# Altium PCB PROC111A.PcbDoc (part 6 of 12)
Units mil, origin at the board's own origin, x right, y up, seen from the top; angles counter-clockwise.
Board outline 7700 x 2300 mil, 6 copper layers (Top Layer, GND 1, SIG 1, SIG 2, GND 2, Bottom Layer), stack 61.062 mil thick; 841 components, 632 nets, 2914 pads, 1627 vias.
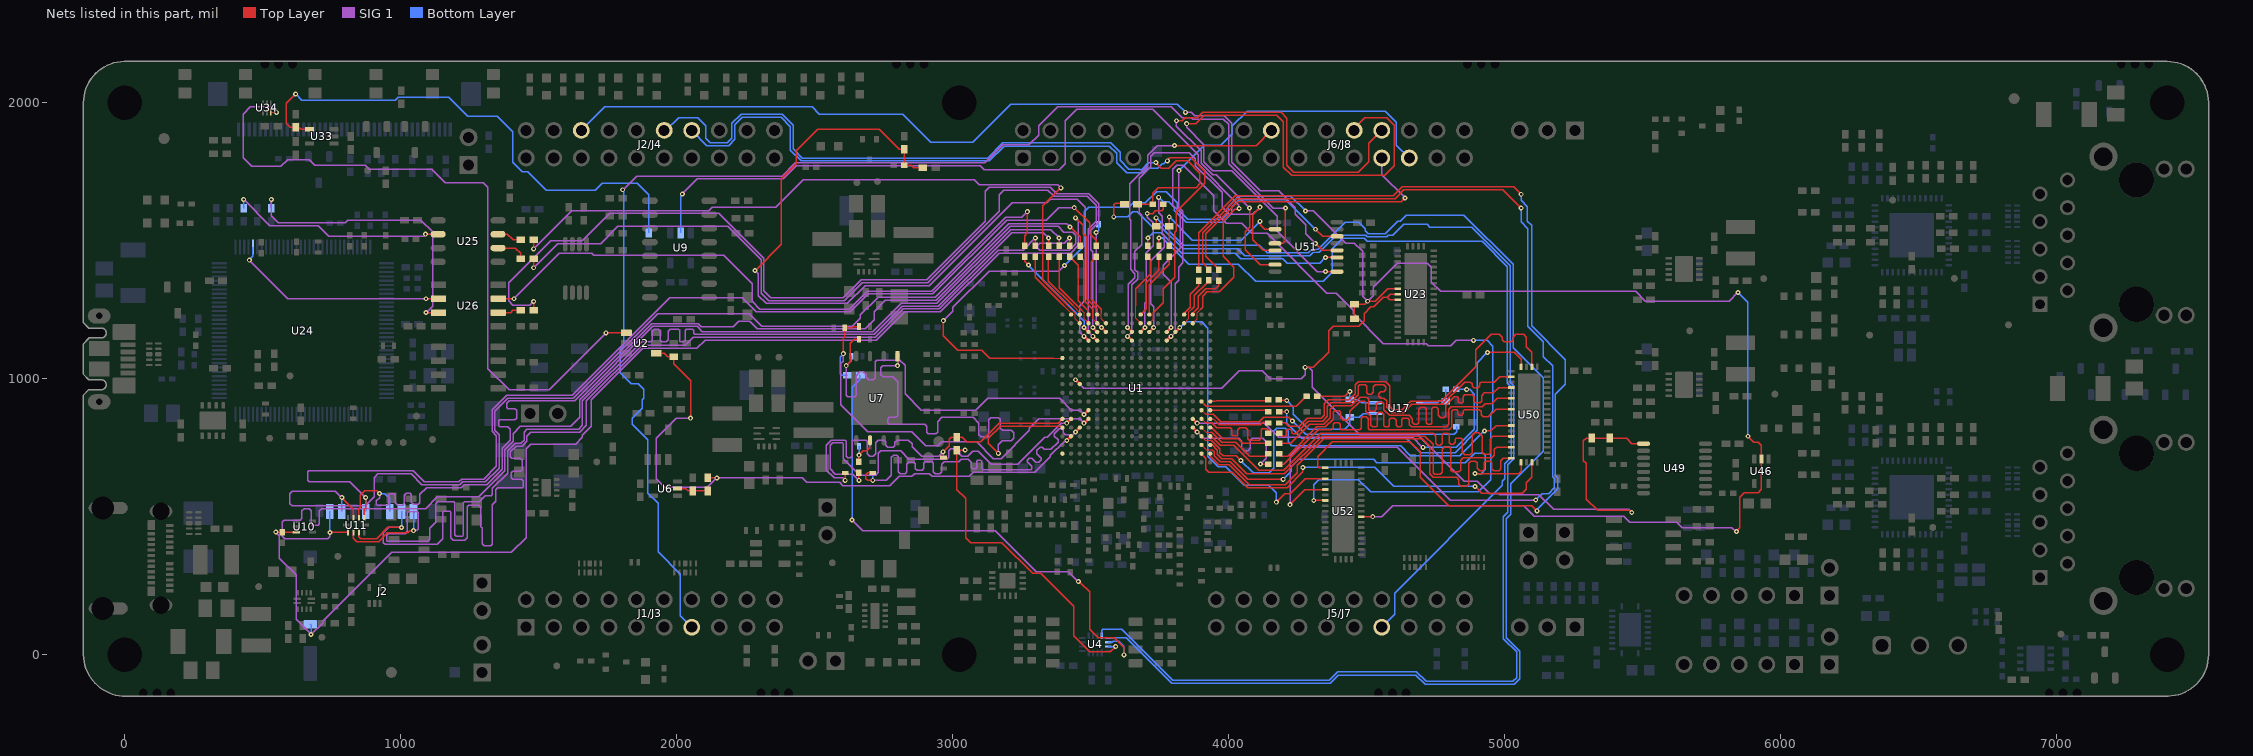
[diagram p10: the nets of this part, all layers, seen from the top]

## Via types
v1: diameter 18, hole 8, Top Layer to Bottom Layer, tented both sides, 1523 vias
v2: diameter 19.68, hole 7.87, Top Layer to Bottom Layer, tented both sides, 104 vias

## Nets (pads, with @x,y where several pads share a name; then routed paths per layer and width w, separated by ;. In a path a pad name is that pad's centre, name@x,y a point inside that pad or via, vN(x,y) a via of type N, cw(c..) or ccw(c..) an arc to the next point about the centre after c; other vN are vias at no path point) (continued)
AM263_MDIO0_MDC_R: R61.2 U1.M17 | length 995.7
  Top Layer w4: U1.M17@3901.07,886.34 3915.59,871.81
  Top Layer w5.3: 3915.59,871.81 3943.38,871.81 3971.5,843.69 4109.91,843.69 4126.4,860.18 4216.95,860.18 v1(4230,847.13)
  Bottom Layer w5.3: v1(4230,847.13) 4278.34,798.79 4816.19,798.79 4825,807.6 4825,825.75 R61.2@4824.96,825.79
AM263_MDIO0_MDIO: R62.1 R64.1 U17.7 | length 125.7
  Bottom Layer w5.3: U17.7@4705.28,913.43 4754.79,913.43 4759.79,918.43 R64.1@4785.59,918.43 R62.1@4785.59,961.7
AM263_MDIO0_MDIO_R: R62.2 U1.N16 | length 1289.2
  Top Layer w10: U1.N16@3869.57,854.84 v1(3885.32,839.09)
  SIG 1 w4.75: v1(3885.32,839.09) 4128.7,839.09 4180.25,787.54 4665.65,787.54 4701.26,751.93 v1(4703.62,751.93)
  Bottom Layer w5.3: v1(4703.62,751.93) 4824.46,751.93 4890,817.46 4890,944.07 4872.46,961.61 v1(4861.92,961.61) 4861.82,961.7 R62.2@4824.96,961.7
AM263_MMC0_CD: J2.9 R40.1 U1.A5 U10.3 | length 4633.3
  Top Layer w5.3: v1(547.23,444.53) R40.1@570.7,444.53 U10.3@613.65,444.53 ; v1(3444.38,1583.21) 3472,1555.59 3472,1525.5 3485,1512.5 3485,1289.81 3523.12,1251.69 U1.A5@3523.12,1232.8
  SIG 1 w4.75: v1(675.15,73.7) 716.63,115.18 716.63,121.7 747.2,152.28 cw(c763.55,142.11) 753.37,158.45 966.68,371.75 1200.92,371.75 1201.9,370.76 1400.23,370.76 1454.17,424.7 1454.17,747.3 1470.09,763.23 1633.46,763.23 1658.14,787.9 1658.14,795.88 1690,827.74 1690,923.63 1876.56,1110.2 2072.97,1110.2 2103.28,1140.51 2723.12,1140.51 2825.46,1242.85 2955.2,1242.85 3168.05,1455.7 3426.54,1455.7 3455.2,1484.37 3455.2,1572.39 v1(3444.38,1583.21)
  SIG 1 w5.3: v1(547.23,444.53) 559.83,431.92 559.83,350.32 620.88,289.27 620.88,127.96 v1(675.15,73.7)
  Bottom Layer w5.3: J2.9@671.97,110.16 675.15,106.98 v1(675.15,73.7)
AM263_MMC0_CLK: J2.5 R33.2 U11.1 | length 3953.5
  Top Layer w5.3: U11.1@867.72,496.58 867.72,526.24 872.76,531.27 v1(872.76,569.45) ; v1(3440,1620) 3495.4,1564.6 3495.4,1526.1 3519,1502.5 R33.2@3519,1482.17
  SIG 1 w4.75: v1(872.76,569.45) 814.65,627.56 668.52,627.56 663.07,633.01 663.07,664 665.85,666.78 1044.33,666.78 1084.97,626.15 1210.08,626.15 1220.34,636.41 1300.64,636.41 1346.64,682.41 1346.64,793.48 1330.7,809.42 1330.7,887.14 1383.73,940.16 1621.25,940.16 1974.63,1293.54 2237.5,1293.54 2288.35,1242.69 2629.26,1242.69 2694.29,1307.71 2927.71,1307.71 3194.99,1574.99 3338.2,1574.99 3383.21,1620 v1(3440,1620)
  Bottom Layer w5.3: J2.5@872.76,519.61 v1(872.76,569.45)
AM263_MMC0_CLK_R: R33.1 U1.B6 | length 271.2
  Top Layer w4: 3537.64,1237.89 3537.64,1218.27 U1.B6@3554.61,1201.3
  Top Layer w5.3: R33.1@3519,1442.8 3500.97,1424.76 3500.97,1288.83 3537.64,1252.16 3537.64,1237.89
AM263_MMC0_CMD: J2.3 R34.2 U11.2 | length 4077.1
  Top Layer w5.3: U11.2@848.04,496.58 848.04,528.5 853.23,533.69 853.23,577.54 869.46,593.77 913.58,593.77 v1(923.09,584.25) ; R34.2@3423,1482.17 v1(3423,1510.23)
  SIG 1 w4.75: v1(923.09,584.25) 923.04,584.2 923.04,568.75 911.91,557.62 911.91,544.51 914.7,541.73 951.21,541.73 955.9,546.42 955.9,578.94 961.21,584.25 975.79,584.25 980,580.04 980,550.86 989.13,541.73 1006.38,541.73 1013.31,548.66 1013.31,578.44 1019.87,585 1033.4,585 1038.36,580.04 1038.36,552.76 1046.12,545 1063.96,545 1069.48,550.51 1069.48,581.06 1093.74,605.32 1219.01,605.32 1230,616.31 1311.05,616.31 1366.74,672 1366.74,747.64 1396.64,777.54 1396.64,817.87 1388.34,826.17 1357.78,826.17 1355,828.95 1355,848.02 1357.78,850.8 1412.66,850.8 1419.52,857.67 1419.52,885.31 1413.06,891.78 1388.15,891.78 1383.19,896.74 1383.19,911.2 1392.05,920.06 1629.58,920.06 1909.52,1200 2077.48,1200 2088.4,1189.08 2203.92,1189.08 2223.99,1209.16 2263.92,1209.16 2292.37,1180.71 2682.56,1180.71 2714.93,1213.08 2714.93,1243.43 2756.08,1284.58 2940.08,1284.58 3207.45,1551.95 3381.28,1551.95 3402.48,1530.75 3434.54,1530.75 3445.15,1520.14 3445.15,1488.53 3422.37,1465.75 3315,1465.75 3308.15,1472.6 3308.15,1484.13 3315,1490.98 3403.75,1490.98 v1(3423,1510.23)
  Bottom Layer w5.3: v1(923.09,584.25) 942.45,584.25 959.37,567.33 J2.3@959.37,519.61
AM263_MMC0_CMD_R: R34.1 U1.A4 | length 238.4
  Top Layer w5.3: R34.1@3423,1442.8 3455,1410.8 3455,1283.11 3489.62,1248.48 3489.62,1234.79 U1.A4@3491.62,1232.8
AM263_MMC0_D0: J2.7 R35.2 U11.3 | length 3978.7
  Top Layer w5.3: v1(786.14,569.45) 828.35,527.24 U11.3@828.35,496.58 ; v1(3425,1550) 3461,1514 R35.2@3461,1482.17
  SIG 1 w4.75: v1(786.14,569.45) 762.96,592.64 607.2,592.64 598.36,583.79 598.36,548.08 606.35,540.09 870.62,540.09 899.81,569.28 899.81,569.45 903.84,573.48 903.84,642.35 917.16,655.66 1037.01,655.66 1076.57,616.1 1214.24,616.1 1224.5,626.36 1306.88,626.36 1356.69,676.18 1356.69,797.65 1340.75,813.58 1340.75,882.97 1387.89,930.11 1625.42,930.11 1930.3,1235 2263.37,1235 2307.61,1190.76 2636.32,1190.76 2664.93,1219.37 2664.93,1231.73 2729.17,1295.98 2937.27,1295.98 3203.29,1562 3413,1562 v1(3425,1550)
  Bottom Layer w5.3: J2.7@786.14,519.61 v1(786.14,569.45)
AM263_MMC0_D0_R: R35.1 U1.B5 | length 267.2
  Top Layer w4: 3507.37,1240.67 3507.37,1217.05 U1.B5@3523.12,1201.3
  Top Layer w5.3: R35.1@3461,1442.8 3474.4,1429.4 3474.4,1285.42 3507.37,1252.45 3507.37,1240.67
AM263_MMC0_D1: J2.8 R36.2 U11.6 | length 3920
  Top Layer w5.3: v1@743.59,443.43 U11.6@808.67,443.43 ; R36.2@3385,1482.17 v1(3385,1510.23)
  SIG 1 w4.75: v1(743.42,443.25) 743.42,427.65 735.66,419.9 580.1,419.9 571.25,428.75 571.25,482.59 576.83,488.16 635.61,488.16 641.85,494.41 641.85,521.85 650.04,530.04 667.74,530.04 675.15,522.63 675.15,472.86 677.93,470.08 700.81,470.08 705.43,474.71 705.43,521.73 713.74,530.04 1090.04,530.04 1132.15,572.15 1282.78,572.15 1376.79,666.15 1376.79,743.48 1406.69,773.38 1406.69,801.15 1433.43,827.89 1615.98,827.89 1648.09,860 1648.09,924.36 1913.68,1189.95 2073.32,1189.95 2092.61,1170.66 2710.63,1170.66 2812.97,1273 2942.71,1273 3209.71,1540 3355.23,1540 v1(3385,1510.23)
  Bottom Layer w5.3: J2.8@742.83,519.61 742.83,443.83 v1(743.42,443.25)
AM263_MMC0_D1_R: R36.1 U1.B4 | length 285.7
  Top Layer w4: 3467.28,1248.59 3475.87,1240 3475.87,1217.05 U1.B4@3491.62,1201.3
  Top Layer w5.3: R36.1@3385,1442.8 3385.16,1442.64 3385.16,1330.71 3467.28,1248.59
AM263_MMC0_D2: J2.1 R37.2 U11.7 | length 4153.8
  Top Layer w5.3: U11.7@828.35,443.43 828.35,422.3 840.72,409.93 919.55,409.93 951.62,442 1025.37,442 1032.84,449.47 1046.02,449.47 v1(1046.12,449.56) ; R37.2@3347,1482.17 v1(3347,1510.23)
  SIG 1 w4.75: v1(1046.12,449.56) 1047.05,450.49 1058.49,450.49 1063.69,455.69 1063.69,514.62 1060.01,518.3 1026.42,518.3 1023.64,515.51 1023.64,447.02 1015.51,438.9 954.26,438.9 948.88,433.52 948.88,413.48 951.66,410.7 1097.49,410.7 1105,418.22 1105,459.17 1126.82,480.99 1126.82,547.21 1134.61,555 1191.87,555 1195.72,551.15 1195.72,434.53 1200.2,430.05 1224.39,430.05 1227.18,432.83 1227.18,551.01 1231.17,555 1283.88,555 1305.26,576.38 1326.88,576.38 1331.54,581.04 1331.54,602.61 1386.84,657.91 1386.84,739.31 1413.79,766.26 1435.36,766.26 1446.64,777.54 1446.64,806.36 1457.25,816.97 1643.88,816.97 1658.14,831.23 1658.14,920.2 1872.34,1134.4 1905.55,1134.4 1910.43,1139.28 1910.43,1172.49 1917.84,1179.9 1932.6,1179.9 1940,1172.5 1940,1140.36 1945.74,1134.61 1962.09,1134.61 1968.71,1141.23 1968.71,1172.99 1975.63,1179.9 2005.96,1179.9 2010.09,1175.76 2010.09,1136.52 2012.88,1133.74 2027.22,1133.74 2030,1136.52 2030,1174.76 2035.14,1179.9 2056.52,1179.9 2060.53,1175.89 2060.53,1165.08 2065,1160.61 2714.79,1160.61 2817.14,1262.95 2946.88,1262.95 3213.88,1529.95 3327.28,1529.95 v1(3347,1510.23)
  Bottom Layer w5.3: J2.1@1045.98,519.61 1046.12,519.48 v1(1046.12,449.56)
AM263_MMC0_D2_R: R37.1 U1.A3 | length 257.6
  Top Layer w4: 3434.29,1265.65 3460.12,1239.82 U1.A3@3460.12,1232.8
  Top Layer w5.3: R37.1@3347,1442.8 3346.11,1441.91 3346.11,1353.83 3434.29,1265.65
AM263_MMC0_D3: J2.2 R38.2 U11.8 | length 4068
  Top Layer w5.3: U11.8@848.04,443.43 848.04,428.2 855.71,420.53 912.66,420.53 953.59,461.46 1002.73,461.46 v1(1002.8,461.53) ; R38.2@3299,1482.17 v1(3299,1510.23)
  SIG 1 w4.75: v1(1002.8,461.53) 955.9,461.53 937.3,442.93 937.3,406.48 943.13,400.65 1131.5,400.65 1152.06,421.21 1152.06,517.3 1154.84,520.08 1179.03,520.08 1181.82,517.3 1181.82,424.87 1190.95,415.75 1231.09,415.75 1240,424.65 1240,535.58 1246.28,541.86 1282.02,541.86 1290,533.88 1290,464.48 1295,459.48 1295,401.57 1301.57,395 1325.64,395 1331.54,400.9 1331.54,543.61 1344.43,556.5 1344.43,597.93 1351.82,605.32 1441.34,605.32 1444.12,608.11 1444.12,630.86 1438.74,636.24 1405.03,636.24 1400,641.28 1400,659.74 1405.26,665 1435.17,665 1440,669.83 1440,704.67 1431.81,712.86 1401.56,712.86 1396.89,717.53 1396.89,735.15 1417.95,756.21 1439.53,756.21 1456.69,773.38 1456.69,792.03 1471.12,806.46 1647.59,806.46 1672.76,831.63 1672.76,920.6 1874.46,1122.31 2030.64,1122.31 2058.89,1150.56 2718.96,1150.56 2821.3,1252.9 2951.04,1252.9 3163.89,1465.75 3254.52,1465.75 v1(3299,1510.23)
  Bottom Layer w5.3: J2.2@1002.68,519.61 1002.8,519.49 v1(1002.8,461.53)
AM263_MMC0_D3_R: R38.1 U1.A2 | length 263.9
  Top Layer w4: 3402.08,1264.29 3428.63,1237.74 U1.A2@3428.63,1232.8
  Top Layer w5.3: R38.1@3299,1442.8 3299,1367.05 3401.76,1264.29 3402.08,1264.29
AM263_MMC0_WP: R41.1 U1.C6 | length 408.5
  Top Layer w10: v1(3538.87,1185.55) U1.C6@3554.61,1169.8
  SIG 1 w4.75: v1(3519.62,1529.88) 3519.62,1204.8 v1(3538.87,1185.55)
  Bottom Layer w5.3: v1(3519.62,1529.88) 3528.01,1538.27 R41.1@3528.01,1560.32
AM263_MUX_EN_GPIO58: R288.2 R290.2 U1.F1 U23.8 U46.2 U52.8 | length 6829.2
  Top Layer w4: 3365.64,1075.32 U1.F1@3397.13,1075.32
  Top Layer w5.3: v1(2965.7,1210.5) 2965.7,1156.45 3018.26,1103.89 3104.61,1103.89 3133.18,1075.32 3365.64,1075.32 ; R290.2@4455.35,1217.93 R288.2@4455.35,1270.9 4493.09,1270.9 v1(4503.13,1280.95) 4530.98,1280.95 4576.22,1326.18 U23.8@4612.24,1326.18 ; U52.8@4479.96,500.32 v1(4521.61,500.32) ; v1(5839.62,447.23) 5839.62,448.1 5851.17,459.65 5851.17,570.96 5866.72,586.5 5917.5,586.5 5930,599 U46.2@5930,709.29 5930,758.65 5918.88,769.76 5902.77,769.76 v1(5880.69,791.85)
  SIG 1 w4.75: v1(2965.7,1210.5) 2999.5,1244.3 2999.5,1258.72 3131.28,1390.5 3384.57,1390.5 v1(3404.94,1410.88) ; v1(4278.41,1608) 4306.08,1608 4422.94,1491.14 4455.36,1491.14 4484.68,1461.82 4484.68,1299.4 v1(4503.13,1280.95) 4523.66,1301.47 4523.66,1331.9 4610.91,1419.15 4719.07,1419.15 4733.22,1405 4733.22,1350.17 4767.09,1316.3 5475,1316.3 5509.44,1281.86 5813.55,1281.86 v1(5844.69,1313) ; v1(4521.61,500.32) 4554.48,500.32 4594.01,539.84 5067.99,539.84 5106.05,501.78 5431.83,501.78 5452.86,480.75 5622.36,480.75 5642.11,461 5823,461 5836.77,447.23 v1(5839.62,447.23)
  Bottom Layer w5.3: v1(3404.94,1410.88) 3475.87,1481.81 3475.87,1604.79 3492.63,1621.55 3637.61,1621.55 3653.1,1637.03 3697.78,1637.03 3738.21,1677.46 3773.35,1677.46 3812.64,1638.18 3812.64,1615.51 3850.47,1577.68 3973.61,1577.68 3998.14,1602.2 3998.14,1623.75 4036.63,1662.24 4224.16,1662.24 v1(4278.41,1608) ; v1(5844.69,1313) 5880.69,1277 v1(5880.69,791.85)
AM263_PORZ: R6.2 R19.1 U1.R2 U2.4 | length 2277
  Top Layer w5.3: U2.4@1925.37,1092.05 1954.75,1092.05 1967.66,1079.13 R6.2@1989.09,1079.13 1989.09,1053.83 2049.68,993.24 v1(2049.68,857.17) ; R19.1@2112.84,641.01 2144.9,641.01 v1(2145,640.91)
  Top Layer w10: v1(3412.88,776.1) U1.R2@3428.63,791.85
  SIG 1 w4.75: v1(2049.68,857.17) 1998.21,857.17 1925,783.96 1925,637.21 1955.51,606.7 2110.79,606.7 v1(2145,640.91) 2455,640.91 2470.94,624.97 2589.96,624.97 2602.03,612.9 2771.96,612.9 2805.87,646.81 2851.93,646.81 2861.54,656.41 2915.4,656.41 2925,646.81 3059.85,646.81 3073.9,660.85 3297.22,660.85 3353.75,717.38 3353.75,722.19 3403.62,772.06 3405.25,772.06 3409.3,776.1 v1(3412.88,776.1)
AM263_PORZ_PB: U2.1 U34.6 | length 2545.1
  Top Layer w4: U34.6@528.78,1965.47 v1(550,1965.47)
  Top Layer w5.3: v1(1743.92,1166.68) 1816.94,1166.68 U2.1@1817.11,1166.85
  SIG 1 w5.3: v1(550,1965.47) 530.48,1985 455,1985 429.13,1959.13 429.13,1800.87 459.24,1770.76 565.76,1770.76 589.52,1794.52 668.66,1794.52 688.66,1774.52 870.82,1774.52 885.82,1759.52 1112.48,1759.52 1161.5,1710.5 1299,1710.5 1315.49,1694.01 1315.49,1037.2 1392.14,960.54 1537.77,960.54 v1(1743.92,1166.68)
AM263_PORZ_RC: C63.1 R19.2 U6.2 | length 113.5
  Top Layer w5.3: U6.2@2002.96,602.39 2032.18,602.39 2040.8,593.77 C63.1@2057.84,593.77 R19.2@2112.84,593.77
AM263_PR0_MDIO0_MDC: R71.1 R73.1 U17.2 | length 445.2
  Top Layer w5.3: R71.1@4181.94,921.65 v1(4210,921.65)
  Bottom Layer w5.3: v1(4210,921.65) 4234.34,897.31 4234.34,871.78 4289.41,816.71 4420,816.71 4438.41,835.13 R73.1@4438.41,860.55 4473.28,860.55 4486.79,874.06 U17.2@4530.08,874.06
AM263_PR0_MDIO0_MDC_R: R71.2 U1.L18 | length 211.2
  Top Layer w5.3: U1.L18@3932.57,917.83 3950.96,917.83 3953.77,920.65 R71.2@4142.57,920.65
AM263_PR0_MDIO0_MDIO: R72.1 R74.1 U17.4 | length 250.1
  Top Layer w5.3: R72.1@4321.3,936.73 4420.89,936.73 v1(4438.41,954.25)
  Bottom Layer w5.3: v1(4438.41,954.25) R74.1@4438.41,924.9 4469.79,924.9 4481.26,913.43 U17.4@4530.08,913.43
AM263_PR0_MDIO0_MDIO_R: R72.2 U1.L17 | length 402.5
  Top Layer w4: U1.L17@3901.07,917.83 3909.88,909.02
  Top Layer w5.3: 3909.88,909.02 3917.72,901.18 4244.38,901.18 4272.73,929.54 4274.74,929.54 R72.2@4281.93,936.73
AM263_PRU_MUX_SEL_GPIO64: R287.2 R289.2 U1.J3 U23.9 U23.10 U49.1 | length 3551.2
  Top Layer w5.3: v1(4276.91,1041.61) 4306.29,1041.61 4361.32,1096.64 4361.32,1173.6 4378.38,1190.65 4470.51,1190.65 4490.24,1210.38 4490.24,1236.09 4515.09,1260.94 4525.97,1260.94 4560.18,1295.16 4574.29,1295.16 ; U23.10@4612.24,1286.81 4582.63,1286.81 4574.29,1295.16 ; U23.9@4612.24,1306.5 4585.63,1306.5 4574.29,1295.16 ; R289.2@5315.31,784.34 5316.14,785.17 R287.2@5380,785.17 5380.85,784.32 5441.07,784.32 5460.59,764.8 U49.1@5502.8,764.8 ; R289.2@5315.31,785.17 5295,785.17 5285,775.17 5285,703.97 5295.66,693.31 5295.66,564.34 5336.94,523.06 5450.55,523.06 5457.78,515.82 v1(5460,515.82)
  Top Layer w10: v1(3444.38,996.57) U1.J3@3460.12,980.83
  SIG 1 w4.75: v1(3444.38,996.57) 3475.05,965.9 3973.85,965.9 4037.36,1029.42 4121.85,1029.42 4150.52,1000.75 4263.26,1000.75 4276.91,1014.4 v1(4276.91,1041.61) 4290,1041.61 4302.46,1029.15 4302.46,969.78 4474.65,797.59 4685.18,797.59 4853.52,629.25 4900.22,629.25 4945.98,583.49 4978.38,583.49 4981.72,580.16 5123.15,580.16 5176.58,526.73 5449.1,526.73 v1(5460,515.82)
AM263_QSPI0_CLK: R26.1 R31.1 U7.6 | length 133.8
  Top Layer w5.3: R26.1@2660,698.65 2660,722.95 2676.45,739.39 2688.55,739.39 2700,750.85 U7.6@2700,776.92
  Bottom Layer w5.3: v1(2660,723.29) 2660.16,723.45 2660.16,754.84 R31.1@2660.31,755
AM263_QSPI0_CLK_R: R26.2 U1.N2 | length 1421.9
  Top Layer w5.3: v1(2660,632.15) R26.2@2660,659.28
  Top Layer w10: v1(3412.88,839.09) U1.N2@3428.63,854.84
  SIG 1 w4.75: v1(2660,632.15) 2637.15,655 2574.16,655 2555.75,673.41 2555.75,759.44 2564.16,767.85 2600.58,767.85 2603.36,765.06 2603.36,710.51 2662.47,651.4 2720.43,651.4 2730.75,661.72 2730.75,729.87 2739.41,738.53 2811.1,738.53 2840.49,709.13 2978.8,709.13 2985,715.33 2985,739.12 2993.08,747.2 3017.67,747.2 3025.75,739.12 3025.75,727.15 3033.28,719.63 3054.5,719.63 3072.03,737.15 3092.03,737.15 3138.53,690.65 3235.65,690.65 3332.34,787.34 3341.97,787.34 3393.72,839.09 v1(3412.88,839.09)
AM263_QSPI0_CSN0: R337.1 U1.P1 U7.1 | length 1571.3
  Top Layer w5.3: v1(2800,1047.52) U7.1@2800,1082.08 ; v1(3164.74,730) 3128.62,766.12 3128.62,784.58 3172.87,828.83 3391.65,828.83 U1.P1@3397.13,823.35
  SIG 1 w4.75: v1(2800,1047.52) 2746.93,1047.52 2739.41,1040 2739.41,1014.98 2747.73,1006.66 2782.3,1006.66 2800,988.96 2800,866.42 2793.83,860.25 2770,860.25 2763.78,854.03 2763.78,840.81 2770,834.59 2899.26,834.59 2905.48,828.37 2905.48,805.71 2910.23,800.96 2939.1,800.96 2945.21,807.07 2945.21,844.7 2960.78,860.27 3074.33,860.27 3094.85,839.75 3094.85,798.06 3103.55,789.36 3124.13,789.36 3130,795.22 3130,851.96 3137.65,859.61 3165.1,859.61 3172.05,852.66 3172.05,821.47 3180.82,812.69 3212.31,812.69 3220,805 3220,784.4 3211.44,775.84 3180,775.84 3164.74,760.58 v1(3164.74,730)
  Bottom Layer w5.3: R337.1@2799.53,1082.25 2799.76,1082.01 2799.76,1047.76 v1(2800,1047.52)
AM263_QSPI0_D0: R27.2 R42.1 R301.1 U1.N1 | length 1448.5
  Top Layer w5.3: v1(2610,632.15) R27.2@2610,659.28 ; R301.1@2966.47,714.56 2965,716.03 v1(2965,735.51) 2987.48,757.99 2987.48,780.94 2994.95,788.42 R42.1@3014.53,788.42 3033.79,788.42 3049.89,772.33 3100.39,772.33 3167.49,839.43 3381.72,839.43 U1.N1@3397.13,854.84
  SIG 1 w4.75: v1(2610,632.15) 2601.25,640.91 2569.85,640.91 2541.67,669.08 2541.67,759.57 2560,777.9 2609.22,777.9 2613.41,773.71 2613.41,718.84 2618.49,713.76 2629.03,713.76 2635.5,720.24 2635.5,773.89 2639.51,777.9 2685,777.9 2690,772.9 2690,728.53 2698.53,720 2711.18,720 2720,728.82 2720,767.9 2730,777.9 2750,777.9 2756.67,771.22 2756.67,759.03 2763.78,751.93 2783.86,751.93 2790,758.07 2790,770 2797.9,777.9 2839.08,777.9 2853.05,763.93 2853.05,753.37 2887.24,719.18 2948.67,719.18 v1(2965,735.51)
AM263_QSPI0_D1: R28.2 R43.1 R336.1 U1.N4 | length 1511.3
  Top Layer w5.3: v1(2603.36,1091.06) 2603.36,1146.18 2608.43,1151.25 R336.1@2608.43,1184.92 2634.52,1184.92 2638.87,1189.27 R28.2@2660,1189.27
  Top Layer w10: v1(3475.87,839.09) U1.N4@3491.62,854.84
  SIG 1 w4.75: v1(2603.36,1091.06) 2603.36,1064.1 2594.76,1055.49 2594.76,906.06 2692.36,808.46 2850.42,808.46 2902.03,756.85 2944.91,756.85 2959.16,771.11 3086.68,771.11 3147.03,710.75 3175.62,710.75 3277.56,812.69 3277.56,821.06 3311.5,855 3459.97,855 v1(3475.87,839.09)
  Bottom Layer w5.3: v1(2603.36,1091.06) 2603.36,1090.6 2591.61,1078.85 2591.61,1018.12 2596.14,1013.59 R43.1@2618.04,1013.59
AM263_QSPI0_D2: R29.2 R338.1 U1.M4 | length 1499.1
  Top Layer w5.3: v1(2614.01,1047.52) 2627.83,1061.34 2627.83,1129.01 2642.36,1143.54 R29.2@2660.31,1143.54
  Top Layer w10: v1(3475.87,870.59) U1.M4@3491.62,886.34
  SIG 1 w4.75: v1(2614.01,1047.52) 2614.01,941.25 2620.26,935 2645,935 2650,940 2650,1011.66 2663.34,1025 2676.41,1025 2686.25,1015.16 2686.25,1005.32 2695,996.57 2711.18,996.57 2718.96,1004.35 2718.96,1061.64 2724.08,1066.77 2808.62,1066.77 2826.86,1048.53 2826.86,945.07 2885.96,885.97 3082.29,885.97 3126.33,930 3386.7,930 3429.99,886.71 3459.75,886.71 v1(3475.87,870.59)
  Bottom Layer w5.3: v1(2614.01,1047.52) 2631.89,1065.4 2631.89,1081.09 R338.1@2633.04,1082.25
AM263_QSPI0_D3: R30.2 R339.1 U1.P3 | length 1434.2
  Top Layer w5.3: v1(2710,632.15) 2691.39,632.15 2685,638.55 2685,652.33 2691.95,659.28 R30.2@2710,659.28
  Top Layer w10: v1(3444.38,807.6) U1.P3@3460.12,823.35
  SIG 1 w4.75: v1(2710,632.15) 2759.64,632.15 2777.49,650 2777.49,715 2786.27,723.79 2796.21,723.79 2803.14,716.86 2803.14,663.72 2810,656.86 2826.86,656.86 2833.86,663.86 2833.86,691.28 2840.46,697.89 2858.45,697.89 2864.84,691.5 2864.84,674.79 2870.76,668.87 2889.43,668.87 2895.56,675 2895.56,694.8 2899.83,699.08 2925.17,699.08 2929.84,694.41 2929.84,663.72 2936.7,656.86 2953.55,656.86 2960.56,663.86 2960.56,690.42 2969.21,699.08 3021.8,699.08 3031.46,708.75 3055.7,708.75 3065.95,698.49 3065.95,680 3071.52,674.44 3083.68,674.44 3087.35,678.11 3087.35,701.04 3091.23,704.92 3099.98,704.92 3104.37,700.52 3104.37,677.59 3111.06,670.9 3281.69,670.9 3285.73,674.95 3285.73,683.39 3270,699.12 3270,705.65 3277.21,712.86 3285.3,712.86 3300.28,697.89 3311.08,697.89 3320,706.8 3320,712.64 3305,727.64 3305,740.65 3316.27,751.93 3324.05,751.93 3331.37,744.6 3355.39,744.6 3381.39,770.6 3381.39,778.98 3368.13,792.23 3368.13,800.93 3385.99,818.79 3395,818.79 3399.75,814.04 3399.75,805.08 3407.7,797.13 3433.91,797.13 v1(3444.38,807.6)
  Bottom Layer w5.3: v1(2710,632.15) R339.1@2710,659.28
AM263_RESETN_PB: R5.1 R179.1 U33.4 | length 1875.5
  Top Layer w5.3: v1(619.09,2032.15) 585.61,1998.67 585.61,1926.14 600.01,1911.74 R179.1@619.09,1911.74 623.76,1907.07 635.75,1907.07 639.08,1903.74 U33.4@669.08,1903.74
  Bottom Layer w5.3: v1(619.09,2032.15) 641.24,2010 980,2010 990,2020 1173.21,2020 1242.71,1950.5 1349.5,1950.5 1405.5,1894.5 1405.5,1784.5 1439.93,1750.07 1459.93,1750.07 1527.36,1682.64 1704.61,1682.64 1730.23,1708.26 1856.74,1708.26 1898.11,1666.89 R5.1@1898.11,1528.29
AM263_RGMII1_RD0: U1.U17 U50.41 | length 1441.6
  Top Layer w5.3: U1.U17@3901.07,728.86 3916.92,713.01 3916.92,672.06 3923.11,665.87 3926.84,662.14 4012.88,662.14 4069.28,605.74 4210.99,605.74 4268.22,662.97 v1(4268.22,678.66) ; v1(4892.25,610) 4916.91,585.33 5063.99,585.33 5078.38,599.72 5078.38,623.99 5098.23,643.84 U50.41@5098.23,696.81
  Bottom Layer w5.3: v1(4268.22,678.66) 4528.37,678.66 4597.02,610 v1(4892.25,610)
AM263_RGMII1_RD1: U1.T17 U50.39 | length 1447.1
  Top Layer w4: U1.T17@3901.07,760.35 3918.04,743.38 3938.58,743.38
  Top Layer w5.3: 3938.58,743.38 3947.09,734.87 3947.09,720.6 3968.41,699.28 4005.73,699.28 4069.13,635.87 v1(4196.91,635.87) ; v1(4892.25,656.62) 5050.48,656.62 5058.86,665 U50.39@5058.86,696.81
  Bottom Layer w5.3: v1(4196.91,635.87) 4226.05,665.01 4226.05,680.89 4252.76,707.6 4524.33,707.6 4535.56,696.38 4857.17,696.38 4891.65,730.85 4921.86,730.85 4930,722.72 4930,671.62 4915,656.62 v1(4892.25,656.62)
AM263_RGMII1_RD2: U1.U18 U50.38 | length 1562.3
  Top Layer w5.3: U1.U18@3932.57,728.86 3932.57,720.13 3964.02,688.68 4001.34,688.68 4073.67,616.34 4204.99,616.34 4248.69,660.04 4248.69,686.74 4344,782.05 4701.59,782.05 4728.64,755 4728.64,655.54 4741.48,642.7 4825.68,642.7 4833.81,634.57 4833.81,618.29 4842.1,610 4861.62,610 4869.79,618.17 4869.79,693.75 4877.3,701.27 4893.73,701.27 4900,695 4900,676.48 4909.26,667.22 4920.4,667.22 4926.16,672.99 4926.16,695 4932.43,701.27 4946.48,701.27 4952.75,695 4952.75,674.02 4959.55,667.22 4978.99,667.22 4985,673.23 4985,702.56 4995,712.56 U50.38@5023.43,712.56
AM263_RGMII1_RD3: U1.T18 U50.36 | length 1562.2
  Top Layer w5.3: U1.T18@3932.57,760.35 3939.95,760.35 3958.48,741.83 3958.48,726.22 3974.82,709.88 4010.12,709.88 4064.6,655.39 4201.47,655.39 4338.73,792.65 4710,792.65 4740,762.65 4740,659.17 4745.88,653.3 4766.09,653.3 4773.6,660.8 4773.6,745.52 4780,751.93 4800,751.93 4805,746.93 4805,668.74 4811.33,662.41 4833.14,662.41 4840,669.27 4840,705 4849.32,714.32 4948.42,714.32 4948.46,714.28 4953.12,714.28 4962.25,723.41 4962.25,744.17 4970,751.93 U50.36@5023.43,751.93
AM263_RGMII1_RX_CTL: U1.R18 U50.34 | length 1562.9
  Top Layer w4: U1.R18@3932.57,791.85 3936.6,791.85 3943.63,784.82
  Top Layer w5.3: 3943.63,784.82 3968.93,759.52 4018.19,759.52 4108.65,669.06 4199.1,669.06 4333.29,803.25 4740.02,803.25 4750.6,792.67 4750.6,766.3 4756.9,760 4766.73,760 4773.6,766.86 4773.6,798.6 4778.27,803.27 4793.52,803.27 4798.18,798.61 4798.18,768.55 4804.21,762.53 4812.61,762.53 4819.63,769.55 4819.63,780.87 4822.73,783.98 4842.02,783.98 4845.83,780.16 4845.83,733.43 4854.34,724.92 4874.92,724.92 4882.8,732.8 4882.8,795.01 4891.88,804.08 4905.45,804.08 4918.18,791.36 4918.18,731.61 4923.45,726.34 4943.6,726.34 4947,729.73 4947,781.84 4956.46,791.3 U50.34@5023.43,791.3
AM263_RGMII1_RXC: U1.R17 U50.32 | length 1440.6
  Top Layer w4: U1.R17@3901.07,791.85 3915.27,777.65 3933.18,777.65
  Top Layer w5.3: 3932.85,777.33 3936.13,777.33 3967.78,745.68 3967.78,731.91 3979.21,720.48 4027.13,720.48 v1(4043.66,703.94) ; v1(4926.16,810.98) 4948.77,810.98 4968.46,830.67 U50.32@5023.43,830.67
  Bottom Layer w5.3: v1(4043.66,703.94) 4088.27,659.34 4147.21,659.34 4162.89,675.02 4162.89,809.86 4173.88,820.85 4204.64,820.85 4215,810.5 4215,771.1 4228.24,757.86 4622.26,757.86 4658.32,721.8 4836.98,721.8 v1(4926.16,810.98)
AM263_RGMII1_TD0: R65.1 U50.29 | length 1135.9
  Top Layer w5.3: R65.1@4181.94,690.82 4199.88,690.82 4323.84,814.78 4371.39,814.78 4378.28,821.67 4378.28,835.71 4383.18,840.61 4397.74,840.61 4402.9,835.45 4402.9,818.99 4407.11,814.78 4474.12,814.78 4480,820.65 4480,857.09 4484.98,862.07 4497.7,862.07 4504.4,855.36 4504.4,820.1 4509.72,814.78 4798.5,814.78 4807.98,824.26 4807.98,882.47 4814,888.49 4825,888.49 4830,883.49 4830,872.95 4835,867.95 4843.22,867.95 4850.27,875 4850.27,883.76 4855,888.49 4907.49,888.49 4914.19,881.78 4914.19,869.4 4921.52,862.07 4940.8,862.07 4968.46,889.72 U50.29@5023.43,889.72
AM263_RGMII1_TD0_R: R65.2 U1.P16 | length 471.4
  Top Layer w5.3: v1(4114.5,690.82) R65.2@4142.57,690.82
  Top Layer w10: U1.P16@3869.57,823.35 v1(3885.32,807.6)
  SIG 1 w4.75: v1(3885.32,807.6) 3909.2,783.72 4035.46,783.72 4046.74,772.44 4046.74,748.46 4055.21,740 4070.39,740 4077.97,747.58 4077.97,776.69 4085,783.72 4122.73,783.72 4134.95,771.51 4134.95,711.26 v1(4114.5,690.82)
AM263_RGMII1_TD1: R66.1 U50.27 | length 1339.1
  Top Layer w5.3: R66.1@4181.94,728.82 4190.76,720 4214.07,720 4319.45,825.38 4350,825.38 4378.28,853.66 4378.28,878.38 4384.72,884.82 4399.45,884.82 4405,879.27 4405,859.76 4415,849.76 4428.18,849.76 4438.41,860 4438.41,881.67 4476.25,919.5 4491.65,919.5 4496.89,914.26 4496.89,882.6 4515,864.49 4515,831.36 4520.98,825.38 4534.53,825.38 4537.63,828.48 4537.63,872.71 4543.35,878.43 4554.79,878.43 4561.41,871.81 4561.41,830.71 4566.74,825.38 4576.97,825.38 4581.5,829.91 4581.5,851.04 4586.72,856.26 4600,856.26 4605.96,850.29 4605.96,830.94 4611.52,825.38 4621.27,825.38 4626.02,830.14 4626.02,852.28 4630,856.26 4649.14,856.26 4654.17,851.23 4654.17,834.39 4663.19,825.38 4787.77,825.38 4797.38,834.99 4797.38,889.9 4806.57,899.09 4918.18,899.09 4928.65,909.57 4952.75,909.57 4972.28,929.09 U50.27@5023.43,929.09
AM263_RGMII1_TD1_R: R66.2 U1.P17 | length 288.2
  Top Layer w4: U1.P17@3901.07,823.35 3918.69,805.72 3935,805.72
  Top Layer w5.3: 3935,806.37 3938.58,806.37 3974.83,770.12 4025,770.12 4075.12,720 4133.75,720 R66.2@4142.57,728.82
AM263_RGMII1_TD2: R67.1 U50.25 | length 1397.3
  Top Layer w5.3: R67.1@4181.94,766.82 4223.56,766.82 4292.78,836.04 4344.62,836.04 4367.68,859.1 4367.68,889.31 4380.8,902.44 4444.19,902.44 4475.75,934 4499.27,934 4507.49,925.78 4507.49,886.99 4511.91,882.57 4528.48,882.57 4535,889.09 4535,909.57 4541.27,915.83 4555.59,915.83 4561.41,910.02 4561.41,888.55 4582.93,867.03 4653.9,867.03 4665.1,855.82 4665.1,842.82 4671.94,835.98 4683.69,835.98 4688.47,840.75 4688.47,890.1 4695,896.63 4710,896.63 4715,891.63 4715,840.98 4720,835.98 4731.9,835.98 4735,839.08 4735,891.63 4740,896.63 4753.09,896.63 4759.46,890.27 4759.46,868.34 4768.7,859.1 4779.05,859.1 4785.35,865.4 4785.35,904 4816.35,935 4827.8,935 4830.91,931.9 4830.91,916.49 4834.37,913.04 4845.73,913.04 4850.27,917.58 4850.27,937.35 4855,942.09 4882.11,942.09 4889.32,934.88 4889.32,917.71 4893.99,913.04 4910,913.04 4915.76,918.79 4915.76,939.06 4925.31,948.62 4958.69,948.62 4978.54,968.46 U50.25@5023.43,968.46
AM263_RGMII1_TD2_R: R67.2 U1.P18 | length 233.4
  Top Layer w5.3: U1.P18@3932.57,823.35 3937.82,823.35 3977.72,783.45 4034.23,783.45 4050.86,766.82 R67.2@4142.57,766.82
AM263_RGMII1_TD3: R68.1 U50.23 | length 1241.2
  Top Layer w5.3: R68.1@4181.94,802.82 4193.01,791.74 4202.79,791.74 4207.41,796.36 4207.41,811.57 4212.86,817.01 4224.36,817.01 4228.87,812.5 4228.87,805.3 4232.85,801.33 4243.08,801.33 4288.39,846.64 4340.22,846.64 4357.08,863.49 4357.08,901.3 4368.81,913.04 4439.8,913.04 4468.54,941.78 4468.54,972.48 4474.4,978.34 4495,978.34 4499.65,973.69 4499.65,950.31 4505.35,944.6 4516.58,944.6 4523.74,951.76 4523.74,972.08 4530,978.34 4560.88,978.34 4568.75,970.47 4568.75,960.11 4561.13,952.5 4550,952.5 4542.55,945.05 4542.55,937.55 4550.1,930 4562.01,930 4572.01,920 4572.01,896.11 4590.49,877.63 4633.54,877.63 4663.15,907.23 4773.6,907.23 4854.51,988.15 4875,988.15 4881.47,981.67 4881.47,974 4887.01,968.46 4903.35,968.46 4910,975.11 4910,983.15 4915,988.15 4962.09,988.15 4981.77,1007.83 U50.23@5023.43,1007.83
AM263_RGMII1_TD3_R: R68.2 U1.N17 | length 387.1
  Top Layer w4: U1.N17@3901.07,854.84 3915.59,840.32
  Top Layer w5.3: 3915.59,840.32 3938.13,840.32 3955.96,822.49 4005,822.49 4011.05,816.45 4011.05,797.15 4014.15,794.05 4029.9,794.05 4033,797.15 4033,815.49 4040,822.49 4061.14,822.49 4068.5,815.14 4068.5,782.7 4073.78,777.42 4111.05,777.42 4118.07,784.44 4118.07,815.96 4121.18,819.06 4137.37,819.06 4142.57,813.87 R68.2@4142.57,802.82
AM263_RGMII1_TX_CTL: R69.1 U50.21 | length 1295
  Top Layer w5.3: R69.1@4181.94,880.82 v1(4210,880.82) ; v1(4937.15,1095.35) 5035.08,1095.35 5058.86,1071.57 U50.21@5058.86,1043.26
  Bottom Layer w5.3: v1(4210,880.82) 4210,839.52 4264.52,785 4642.94,785 4695.53,732.4 4819.93,732.4 4900.6,813.07 4900.6,1058.8 v1(4937.15,1095.35)
AM263_RGMII1_TX_CTL_R: R69.2 U1.M18 | length 212.3
  Top Layer w5.3: U1.M18@3932.57,886.34 4137.05,886.34 R69.2@4142.57,880.82
AM263_RGMII1_TXC: R70.1 U50.19 | length 1400.8
  Top Layer w5.3: R70.1@4181.94,839.82 4182.12,840 4205,840 4217.39,827.61 4254.37,827.61 4284,857.24 4335.83,857.24 4346.48,867.88 4346.48,909.94 4360.17,923.64 4435.41,923.64 4457.94,946.17 4457.94,977.68 4469.2,988.94 4568.92,988.94 4582.61,975.25 4582.61,900.5 4594.88,888.23 4629.15,888.23 4658.76,917.83 4766.07,917.83 4768.43,920.2 4771.57,920.2 4895.12,1043.75 4895.12,1105.39 4951.04,1161.31 4980,1161.31 4990.23,1151.08 4990.23,1141.76 4998.07,1133.92 5022.94,1133.92 5030,1140.98 5030,1151.31 5040,1161.31 5068.14,1161.31 5078.38,1151.06 5078.38,1116.01 5098.23,1096.17 U50.19@5098.23,1043.26
AM263_RGMII1_TXC_R: R70.2 U1.N18 | length 223
  Top Layer w4: U1.N18@3932.57,854.84 3943.26,854.84 3954.3,843.8
  Top Layer w5.3: 3954.3,843.8 3965,833.09 4114.3,833.09 4124.02,842.82 R70.2@4142.57,842.82
AM263_SAFETY_ERRORN: R258.1 R268.1 R272.1 U1.D4 | length 3043.5
  Top Layer w5.3: v1(2283.37,1392.21) 2379.29,1488.13 2379.29,1725.22 2433.47,1779.4 2433.47,1825.74 2511.47,1903.74 2734.26,1903.74 2806.06,1831.94 R258.1@2824.53,1831.94 2824.68,1831.79 R272.1@2824.68,1773.35 2825.04,1773.7 2850,1773.7 2858.24,1765.46 R268.1@2891.38,1765.46
  Top Layer w10: v1(3475.87,1154.06) U1.D4@3491.62,1138.31
  SIG 1 w4.75: v1(2283.37,1392.21) 2295.05,1380.53 2295.05,1301.32 2323.53,1272.84 2616.78,1272.84 2681.89,1337.95 2914.45,1337.95 3215.07,1638.57 3339.88,1638.57 3352.41,1651.11 3450.33,1651.11 3480.27,1621.17 3480.27,1284.22 3460.5,1264.45 3460.5,1169.43 v1(3475.87,1154.06)
AM263_SD_ENABLE_GPIO122: U1.B16 U9.2 | length 3120.8
  Top Layer w4: U1.B16@3869.57,1201.3 3885.32,1217.05 3885.32,1240 3897.49,1252.17
  Top Layer w5.3: 3897.49,1252.17 3904.95,1259.63 3904.95,1299.18 3912.27,1306.5 3920.6,1314.83 3965.9,1314.83 4018.83,1367.76 4018.83,1404.78 3979.11,1444.5 3979.11,1573.48 4020.65,1615.03 4035.17,1615.03 v1(4037.6,1617.46)
  SIG 1 w4.75: v1(2020,1670) 2074.71,1724.71 2385.69,1724.71 2433.09,1772.12 3098.89,1772.12 3113.74,1757.27 3386.53,1757.27 3408.06,1778.8 3408.06,1935 3449.1,1976.04 3723.96,1976.04 3889.07,1810.93 3889.07,1776.74 4036.32,1629.49 4036.32,1618.73 v1(4037.6,1617.46)
  Bottom Layer w5.3: U9.2@2013.97,1528.43 2013.97,1660.55 2020,1666.58 v1(2020,1670)
AM263_SDFM0_CLK1: J6/J8.74 R369.1 | length 1105.5
  Top Layer w5.3: R369.1@3963.34,1395.29 3963.34,1397.25 3916.16,1444.44 3916.16,1525.52 4033,1642.36 4625.51,1642.36 v1(4638.5,1655.35)
  SIG 1 w5.3: J6/J8.74@4554.17,1800 4554.17,1739.68 v1(4638.5,1655.35)
AM263_SDFM0_CLK1_R: R369.2 U1.A16 | length 180.4
  Top Layer w5.3: U1.A16@3869.57,1232.8 3869.57,1237.4 3890,1257.83 3890,1299.22 3916.21,1325.43 3950.92,1325.43 3962.83,1337.34 3962.83,1353.49 R369.2@3963.34,1354
AM263_SDFM0_CLK2: R370.1 U52.26 | length 3850.1
  Top Layer w5.3: R370.1@3927.56,1395.72 3927.56,1397.69 3905.56,1419.7 3905.56,1529.91 4028.61,1652.96 4602.96,1652.96 4634.76,1684.76 4993.4,1684.76 v1(5059.51,1618.66) ; v1(4222.19,543.86) 4222.19,546.09 4274.84,598.74 U52.26@4350.04,598.74
  SIG 1 w4.75: v1(4222.19,543.86) 4222.19,721.23 4252.89,751.93 4610.56,751.93 4802,560.49 5111.73,560.49 v1(5112.15,560.91)
  Bottom Layer w5.3: v1(5059.51,1618.66) 5059.51,1568.49 5084,1544 5084,1190.01 5140.12,1133.89 5140.12,1080.61 5172.88,1047.86 5172.88,645.76 5180,638.64 5180,604.57 5159.38,583.95 5135.2,583.95 v1(5112.15,560.91)
AM263_SDFM0_CLK2_R: R370.2 U1.B15 | length 195
  Top Layer w4: U1.B15@3838.08,1201.3 3855.7,1218.92 3855.7,1242.42 3865,1251.72
  Top Layer w5.3: 3865,1251.72 3875,1261.72 3875,1302.48 3919.27,1346.75 3923.01,1346.75 3930.21,1353.95 R370.2@3930.21,1355.92
AM263_SDFM0_CLK3: R371.1 U52.22 | length 3686
  Top Layer w5.3: R371.1@3890.45,1395.04 3890.45,1529.8 4024.22,1663.56 4595.97,1663.56 4627.77,1695.36 5032.8,1695.36 v1(5059.51,1668.66) ; U52.22@4350.04,677.48 4327.74,677.48 4321.48,683.74 4321.48,717.38 4375.54,771.45 4656.49,771.45 4692.94,735 4692.94,643.67 4796.49,540.11 5098.17,540.11 v1(5116.52,521.76)
  Bottom Layer w5.3: v1(5059.51,1668.66) 5059.51,1646.49 5082,1624 5082,1571.5 5097,1556.5 5097,1192 5219.52,1069.48 5219.52,980.06 5183.48,944.01 5183.48,650.15 5192.59,641.03 5192.59,601.02 5116.52,524.95 v1(5116.52,521.76)
AM263_SDFM0_CLK3_R: R371.2 U1.A15 | length 144.6
  Top Layer w5.3: U1.A15@3838.08,1232.8 3838.08,1237.95 3860,1259.87 3860,1306.51 3890.45,1336.96 R371.2@3890.45,1355.67
AM263_SDFM0_D2: U1.C13 U52.28 | length 3407.5
  Top Layer w5.3: v1(4307.78,559.37) U52.28@4350.04,559.37
  Top Layer w10: U1.C13@3775.09,1169.8 v1(3790.83,1185.55)
  SIG 1 w4.75: v1(3790.83,1185.55) 3790.83,1349.17 3761.98,1378.02 3761.98,1412.26 3823.56,1473.84 3823.56,1602.64 3797.48,1628.72 3797.48,1759.48 3811.35,1773.35 3835.25,1773.35 3945.91,1662.69 3945.91,1609.11 3991.21,1563.81 4046.84,1563.81 4083.07,1527.58 4138.57,1527.58 4355.34,1310.8 4388.52,1310.8 4450.1,1249.22 4450.1,1236.68 4560.01,1126.77 4715.99,1126.77 4723.45,1119.3 4804.28,1119.3 4824.03,1139.06 v1@4886.55,1139.06
  Bottom Layer w5.3: v1(4307.78,559.37) 4307.78,616.95 4325.83,635 4469.38,635 4513.91,590.48 4903.89,590.48 4948.42,635 4948.42,873.75 4956.67,882.01 4956.67,1118.33 4935.59,1139.41 v1(4886.55,1139.41)
AM263_SDFM0_D3: U1.C14 U52.24 | length 1157.1
  Top Layer w5.3: v1(4172.26,552.78) 4202.78,583.31 4221.77,583.31 4276.58,638.11 U52.24@4350.04,638.11
  Top Layer w10: U1.C14@3806.58,1169.8 v1(3822.33,1185.55)
  Bottom Layer w5.3: v1(3822.33,1185.55) 3842.66,1205.88 3902.2,1205.88 3924.54,1183.53 3924.54,718.57 3962.12,680.99 3988.9,680.99 4055.11,614.78 4145.21,614.78 4172.26,587.74 v1(4172.26,552.78)
AM263_SFDM0_D1: J6/J8.73 U1.D13 | length 1707.4
  Top Layer w10: U1.D13@3775.09,1138.31 v1(3790.83,1154.06)
  SIG 1 w4.75: v1(3790.83,1154.06) 3806.21,1169.43 3806.21,1345.21 3818,1357 3818,1404.28 3833.61,1419.89 3833.61,1606.81 3818.08,1622.34 3818.08,1752.68 v1(3819.5,1754.1)
  Bottom Layer w5.3: v1(3819.5,1754.1) 3911.18,1845.78 3971.38,1845.78 4013.14,1887.54 4013.14,1917 4066.01,1969.88 4567.44,1969.88 4607.29,1930.03 4607.29,1846.89 J6/J8.73@4654.17,1800
AM263_SOP0: R42.2 U4.15 | length 1174.1
  Top Layer w5.3: v1(3045,741.81) 3044.37,741.17 R42.2@3014.53,741.17 3014.53,598.79 3046.58,566.74 3046.58,423.42 3064.36,405.64 3178.24,405.64 3288.93,294.95 3319.12,294.95 3437.63,176.44 3437.63,69.09 3496.46,10.27 3570.42,10.27 v1(3590.06,29.91)
  Bottom Layer w5.3: U4.15@3563.32,29.91 v1(3590.06,29.91)
AM263_SOP1: R43.2 U4.14 | length 1917.1
  Top Layer w5.3: v1@3454.77,264.31 3458.21,264.31 3462.52,260 3463.84,260 3495.4,228.44 3495.4,93.33 3526.8,61.93 3585.65,61.93 3620,27.58 v1(3620,0)
  SIG 1 w4.75: v1(2635,488.11) 2673.41,449.7 3154.65,449.7 3303.03,301.32 3418.77,301.32 v1(3454.77,265.31)
  Bottom Layer w5.3: v1(2635,488.11) 2635,968.96 2662.97,996.93 2662.97,1011.27 R43.2@2665.28,1013.59 ; U4.14@3563.32,45.65 3578.2,45.65 3581.98,49.43 3601.85,49.43 3620,31.28 v1(3620,0)
AM263_SOP2: R173.2 U4.13 | length 4761.9
  Top Layer w5.3: R173.2@3736.97,1552.62 v1(3736.97,1583.21)
  Bottom Layer w5.3: U4.13@3563.32,61.4 3627.95,61.4 3793.03,-103.68 4367.47,-103.68 4396.69,-74.46 4678.04,-74.46 4710.91,-107.34 5033.65,-107.34 5054.17,-86.81 5054.17,13.72 5005.35,62.54 5005.35,493.22 5021.62,509.5 5021.62,619.83 5139.73,737.94 5139.73,1003.66 5030.96,1112.44 5030.96,1414.13 4851.7,1593.39 4643.41,1593.39 4620.75,1570.73 4612.72,1570.73 4567.2,1525.21 4505.8,1525.21 4494.36,1536.65 4494.36,1543.31 4470.98,1566.7 4421.23,1566.7 4324.17,1469.65 4301.52,1469.65 4288.06,1456.19 4138.81,1456.19 4110.37,1484.64 3835.54,1484.64 v1(3736.97,1583.21)
AM263_SOP3: R174.2 U4.12 | length 4876.6
  Top Layer w5.3: v1(3583.14,1587.05) 3583.82,1587.73 3583.82,1630.47 3590,1636.65 R174.2@3621.82,1636.65
  Bottom Layer w5.3: U4.12@3539.69,69.28 3539.69,87.41 3544.11,91.82 3612.52,91.82 3794.54,-90.2 3794.85,-90.2 3797.73,-93.08 4363.08,-93.08 4395.01,-61.15 4679.72,-61.15 4715.31,-96.74 5029.26,-96.74 5042.62,-83.38 5042.62,10.28 4994.52,58.38 4994.52,499.62 5010.6,515.7 5010.6,688.49 5033.1,710.98 5033.1,975.25 5020.36,987.99 5020.36,1409.74 4880.22,1549.88 4728.64,1549.88 4719,1559.52 4633.02,1559.52 4593.5,1520 4576.98,1520 4571.59,1514.61 4501.41,1514.61 4496.02,1520 4389.51,1520 4328.57,1459.05 4305.91,1459.05 4292.46,1445.59 4058.16,1445.59 4033.26,1470.5 3834.69,1470.5 3755.78,1549.41 3725.05,1549.41 3668.59,1605.87 3651.91,1605.87 3633.1,1587.05 v1(3583.14,1587.05)
AM263_SPI0_CLK: R169.1 R173.1 U51.2 | length 570
  Top Layer w5.3: v1(3784.21,1586.34) R173.1@3784.21,1552.62 3784.21,1482.95 R169.1@3785,1482.17 ; v1(4113.16,1570.73) 4113.16,1558.73 4130,1541.89 U51.2@4167.8,1541.89
  Bottom Layer w5.3: v1(3784.21,1586.34) 3867.94,1502.62 4045.05,1502.62 v1(4113.16,1570.73)
AM263_SPI0_CLK_PR0_PRU0_GPIO16: J1/J3.7 U51.4 | length 4690.4
  Top Layer w5.3: U51.4@4167.8,1490.71 4195.71,1490.71 4205,1500 v1(4205,1618.66)
  SIG 1 w4.75: v1(1804,1685) 1805.43,1685 1855.2,1734.76 2381.52,1734.76 2428.93,1782.17 3115.59,1782.17 3180.65,1847.22 3276.04,1847.22 3311.44,1882.63 3311.44,1917.7 3379.84,1986.09 3792.04,1986.09 3831.91,1946.22 3863.46,1946.22 3868.92,1940.76 3980.41,1940.76 3999.68,1921.49 3999.68,1779.92 4160.93,1618.66 v1(4205,1618.66)
  Bottom Layer w5.3: v1(1804,1685) 1808.18,1680.82 1808.18,1120.03 1794.52,1106.37 1794.52,1022.03 1834.79,981.77 1860.16,981.77 1880,961.93 1880,929.5 1874.06,923.56 1874.06,892.47 1838.42,856.83 1838.42,835.61 1895.25,778.79 1895.25,586.04 1932.6,548.69 1932.6,372.89 2013.14,292.35 2013.14,141.04 J1/J3.7@2054.17,100
AM263_SPI0_CLK_R: R169.2 U1.A11 | length 240.2
  Top Layer w5.3: U1.A11@3712.09,1232.8 3712.09,1264.29 3712.09,1341.32 3785,1414.23 R169.2@3785,1442.8
AM263_SPI0_CS0: U1.C11 U51.14 | length 1318.6
  Top Layer w5.3: v1(4314,1541.89) 4339.59,1516.3 U51.14@4392.2,1516.3
  Top Layer w10: U1.C11@3712.09,1169.8 v1(3727.84,1185.55)
  SIG 1 w4.75: v1(3727.84,1185.55) 3727.84,1261.09 3716.86,1272.07 3716.86,1428.09 3766.25,1477.48 3766.25,1518.2 3759.34,1525.11 3759.34,1588.06 3745.87,1601.53 v1(3745.87,1657.51)
  Bottom Layer w5.3: v1(3745.87,1657.51) 3762.33,1641.05 3782.15,1641.05 3802.04,1621.17 3802.04,1611.12 3846.08,1567.08 3978,1567.08 4010.64,1599.71 4010.64,1621.26 4038.05,1648.67 4207.21,1648.67 v1(4314,1541.89)
AM263_SPI0_CS0_PR0_PRU0_GPIO8: J2/J4.18 U51.12 | length 3218.3
  Top Layer w5.3: v1(4314,1490.71) 4339.59,1465.12 U51.12@4392.2,1465.12
  SIG 1 w4.75: 4180.46,1680.85 4241.5,1619.82 4241.5,1595.5 4279.7,1557.3 4279.7,1525 v1(4314,1490.71)
  SIG 1 w5.3: v1(3843.13,1965.47) 3864.1,1965.47 3876.74,1952.83 3982.94,1952.83 4010,1925.77 4010,1784.19 4113.34,1680.85 4180.46,1680.85
  Bottom Layer w5.3: J2/J4.18@1654.17,1900 1739.17,1985 2490,1985 2515.89,1959.11 2819.11,1959.11 2920.33,1857.89 3072.13,1857.89 3209.23,1995 3813.61,1995 v1(3843.13,1965.47)
AM263_SPI0_D0: J2/J4.15 R170.1 R174.1 | length 2660.4
  Top Layer w5.3: R174.1@3669.07,1631.65 R170.1@3723.62,1631.65 3723.62,1671.63 3744.03,1692.03 3881.62,1692.03 3895.5,1705.92 3895.5,1745.07 3851.05,1789.52 3808.79,1789.52 3782.77,1763.5 3754.74,1763.5 3735.69,1782.55 v1(3735.69,1783.19)
  Bottom Layer w5.3: J2/J4.15@1954.17,1900 1960.8,1900 2006.52,1945.72 2075.32,1945.72 2105,1916.04 2105,1872.45 2121.67,1855.78 2183.04,1855.78 2199.65,1872.4 2199.65,1925.37 2232.65,1958.37 2381.44,1958.37 2421.67,1918.14 2421.67,1832.65 2454.45,1799.88 3125.93,1799.88 3180.83,1854.78 3572.11,1854.78 3606.37,1820.52 3606.37,1791.16 3637.58,1759.95 3677.25,1759.95 3679.32,1757.88 3683.71,1757.88 3709.02,1783.19 v1(3735.69,1783.19)
AM263_SPI0_D0_R: R170.2 U1.C10 | length 544.5
  Top Layer w5.3: v1(3704.48,1598.71) 3724.86,1598.71 3734.15,1608 3757.3,1608 3762.99,1613.69 R170.2@3762.99,1636.65
  Top Layer w10: U1.C10@3680.6,1169.8 v1(3696.35,1185.55)
  SIG 1 w4.75: v1(3696.35,1185.55) 3696.35,1273.88 3700.91,1278.45 3700.91,1456.6 3726.25,1481.94 3726.25,1565.1 3705.21,1586.14 3705.21,1597.99 v1(3704.48,1598.71)
AM263_SPI0_D1: J2/J4.14 U1.B11 | length 2823.8
  Top Layer w4: U1.B11@3712.09,1201.3 3726.62,1215.82
  Top Layer w5.3: 3726.62,1215.82 3726.62,1239.62 3763.25,1276.24 3763.25,1326.71 3804.89,1368.36 3804.89,1531.53 3810.01,1536.64 3810.01,1605.44 3912.92,1708.35 3912.92,1751.14 3864.07,1800 3855.56,1800 3855.44,1800.12 3786.6,1800.12 3779.2,1792.72 v1@3778.91,1792.72
  Bottom Layer w5.3: J2/J4.14@2054.17,1900 2109.09,1845.09 2187.34,1845.09 2210.25,1868.01 2210.25,1920.98 2236.34,1947.07 2377.76,1947.07 2411.07,1913.75 2411.07,1828.26 2450.06,1789.28 3131.72,1789.28 3185.63,1843.19 3567.63,1843.19 3594.23,1816.59 3594.23,1803.86 3594.27,1803.82 3594.27,1783.64 3630.63,1747.28 3688.1,1747.28 3703.08,1762.26 3742.38,1762.26 3758.4,1778.29 3764.64,1778.29 3776.03,1789.68 v1(3777.21,1789.68)
AM263_SPI1_CLK: J5/J7.47 R171.1 | length 3018.4
  Top Layer w5.3: R171.1@3747,1482.17 v1(3747,1510.23)
  Bottom Layer w5.3: v1(3747,1510.23) 3759.62,1510.23 3854.72,1415.13 4034.73,1415.13 4097.08,1352.78 4342.04,1352.78 4375.42,1386.16 4375.42,1471.12 4413.7,1509.4 4491.63,1509.4 4501.85,1499.18 4821.53,1499.18 4823.09,1497.63 4917.48,1497.63 5009.76,1405.35 5009.76,983.6 5022.5,970.86 5022.5,715.37 5000,692.88 5000,637.03 4991.41,628.44 4991.41,613.45 4600.57,222.61 4600.57,146.4 J5/J7.47@4554.17,100
AM263_SPI1_CLK_R: R171.2 U1.A10 | length 237.5
  Top Layer w5.3: U1.A10@3680.6,1232.8 3701.19,1253.38 3701.19,1347.25 3747,1393.06 R171.2@3747,1442.8
AM263_SPI1_CS0: J6/J8.58 U1.C9 | length 1177.7
  Top Layer w5.3: v1(3803.46,1845.18) 4099.35,1845.18 J6/J8.58@4154.17,1900
  Top Layer w10: v1(3633.35,1185.55) U1.C9@3649.1,1169.8
  SIG 1 w4.75: v1(3633.35,1185.55) 3635.57,1187.77 3635.57,1264.29 3635.57,1271.3 3635.67,1271.4 3635.67,1307.3 3635.57,1307.4 3635.57,1341.87 3659.25,1365.55 3659.25,1381.5 3644.5,1396.25 3644.5,1574.62 3640.75,1578.37 3640.75,1707.05 3706.4,1772.69 3706.4,1810.39 3741.18,1845.18 v1(3803.46,1845.18)
AM263_SPI1_D0: R172.1 U51.11 | length 776.2
  Top Layer w5.3: R172.1@3707,1482.17 v1(3707,1510.23) ; v1(4350,1439.53) U51.11@4392.2,1439.53
  Bottom Layer w5.3: v1(3707,1510.23) 3726.52,1529.75 3755.09,1529.75 3829.38,1455.46 4022.9,1455.46 4043.37,1434.99 4195,1434.99 4211.53,1418.46 4328.94,1418.46 v1(4350,1439.53)
AM263_SPI1_D0_PR0_PRU0_GPIO13: J6/J8.55 U51.9 | length 2133.4
  Top Layer w5.3: v1(3847.52,1924.18) 3879.75,1924.18 3910.44,1954.87 4174.29,1954.87 4198.04,1931.12 4198.04,1766.96 4227.24,1737.76 4565.23,1737.76 4598.76,1771.3 4598.76,1918.4 4571.89,1945.27 4492.2,1945.27 4454.17,1907.24 J6/J8.55@4454.17,1900 ; v1(4350,1388.35) U51.9@4392.2,1388.35
  SIG 1 w5.3: v1(3847.52,1924.18) 3847.52,1910.69 3910,1848.21 3910,1786.14 3942.04,1754.1 4010.89,1754.1 4175.26,1589.73 4175.26,1533.91 4320.83,1388.35 v1(4350,1388.35)
AM263_SPI1_D0_R: R172.2 U1.B10 | length 274
  Top Layer w4: 3662.98,1264.29 3662.98,1218.92 U1.B10@3680.6,1201.3
  Top Layer w5.3: 3662.98,1264.29 3662.14,1265.13 3662.14,1325.98 3714.6,1378.44 3714.6,1435.2 R172.2@3707,1442.8
AM263_SPI1_D1: U1.D9 U51.5 | length 1502.3
  Top Layer w5.3: v1(4113.16,1621.81) 4086.08,1594.72 4086.08,1504.63 4125.59,1465.12 U51.5@4167.8,1465.12
  Top Layer w10: v1(3633.35,1154.06) U1.D9@3649.1,1138.31
  SIG 1 w4.75: v1(3633.35,1154.06) 3648.73,1169.43 3648.73,1275.62 3648.35,1276 3648.35,1340.45 3669.3,1361.39 3669.3,1385.66 3660,1394.96 3660,1462 3683.7,1485.7 3683.7,1592.33 3675,1601.03 3675,1727.09 3716.45,1768.53 3716.45,1806.16 3729.69,1819.4 3857.1,1819.4 3879.02,1797.47 3879.02,1772.21 3976.06,1675.18 3976.06,1621.6 4001.92,1595.74 4087.1,1595.74 v1(4113.16,1621.81)
AM263_SPI1_D1_PR0_PRU0_GPIO14: J6/J8.54 U51.7 | length 1769.7
  Top Layer w5.3: v1(3810,1935) 3830.73,1935 3841.68,1945.95 3886.53,1945.95 3906.05,1965.47 4189.53,1965.47 4210.63,1944.37 4210.63,1773.6 4235.86,1748.36 4468.6,1748.36 4507.34,1787.1 4507.34,1853.17 J6/J8.54@4554.17,1900 ; v1(4075,1618.66) 4075,1549.19 4059.47,1533.66 4059.47,1467.63 4113.16,1413.94 U51.7@4167.8,1413.94
  SIG 1 w5.3: v1(3810,1935) 3810,1915.82 3899.4,1826.43 3899.4,1781.75 3942.67,1738.48 3955.18,1738.48 v1(4075,1618.66)
AM263_TCK: R324.1 U1.B3 | length 2631.6
  Top Layer w4: 3412.54,1268.51 3444.38,1236.67 3444.38,1217.05 U1.B3@3460.12,1201.3
  Top Layer w5.3: v1(1481.5,1470.83) R324.1@1481.5,1503.35 ; v1(3391.39,1692.03) 3326.63,1627.28 3326.63,1356.42 3412.54,1270.52 3412.54,1268.51
  SIG 1 w4.75: v1(1481.5,1470.83) 1620.28,1609.61 2115.99,1609.61 2128.18,1621.81 2358.64,1621.81 2458.7,1721.87 3078.06,1721.87 3096.19,1703.74 3379.68,1703.74 v1(3391.39,1692.03)
AM263_TCK_R: R324.2 U25.7 | length 90.4
  Top Layer w5.3: U25.7@1352.36,1523.86 1386.44,1523.86 1406.95,1503.35 R324.2@1434.25,1503.35
AM263_TCK_XDS: R133.1 U25.2 | length 795.1
  Top Layer w5.3: v1(1090,1523.86) U25.2@1135.36,1523.86
  SIG 1 w4.75: v1(430.73,1650) 525.73,1555 701.3,1555 739.42,1516.88 1083.02,1516.88 v1(1090,1523.86)
  Bottom Layer w5.3: R133.1@430.5,1617.63 430.5,1649.77 v1(430.73,1650)
AM263_TDI: R326.1 U1.C5 | length 3378.7
  Top Layer w5.3: R326.1@1481.5,1248.01 v1(1481.5,1280.54)
  Top Layer w10: v1(3507.37,1185.55) U1.C5@3523.12,1169.8
  SIG 1 w4.75: v1(1481.5,1280.54) 1468.09,1267.13 1405.65,1267.13 1390.75,1282.03 1390.75,1347.97 1542.9,1500.12 1658.12,1500.12 1757.56,1599.56 2151.91,1599.56 2315.15,1436.32 2315.15,1319.32 2340.51,1293.95 2602.93,1293.95 2667.47,1358.5 2905.8,1358.5 3117.56,1570.26 3117.56,1680 3131.25,1693.69 3353.7,1693.69 3376.19,1671.21 3491.7,1671.21 3529.24,1633.66 3529.24,1566.73 3500.37,1537.85 3500.37,1467.16 3507.37,1460.16 v1(3507.37,1185.55)
AM263_TDI_R: R326.2 U26.2 | length 84.3
  Top Layer w5.3: U26.2@1353.27,1240 1398.12,1240 1406.13,1248.01 R326.2@1434.25,1248.01
AM263_TDI_XDS: R135.1 U26.7 | length 1054.4
  Top Layer w5.3: v1(1091.37,1240) U26.7@1136.73,1240
  SIG 1 w4.75: v1(530.73,1650) 530.73,1591.41 556.54,1565.6 798.67,1565.6 807.59,1574.52 1072.37,1574.52 1115,1531.9 1115,1263.63 v1(1091.37,1240)
  Bottom Layer w5.3: R135.1@530.5,1617.63 530.5,1649.77 v1(530.73,1650)
AM263_TDO: R7.2 U26.3 | length 2380
  Top Layer w5.3: U26.3@1353.27,1290 v1(1410,1290) ; R7.2@3260,1482.17 3260,1518.5 3270,1528.5 v1(3270,1605.5)
  SIG 1 w4.75: v1(1410,1290) 1574.56,1454.56 1692.76,1454.56 1700,1447.32 2170.9,1447.32 2273.42,1344.8 2273.42,1280.13 2300.82,1252.74 2625.1,1252.74 2690.12,1317.76 2923.26,1317.76 3191.5,1586 3250.5,1586 v1(3270,1605.5)
AM263_TDO_R: R7.1 U1.C4 | length 368.9
  Top Layer w5.3: R7.1@3260,1442.8 3260.06,1442.74 3260.06,1426.14 v1(3274.12,1412.07)
  Top Layer w10: v1(3475.87,1185.55) U1.C4@3491.62,1169.8
  Bottom Layer w5.3: v1(3274.12,1412.07) 3274.12,1410.88 3475.87,1209.13 v1(3475.87,1185.55)
AM263_TDO_XDS: U24.37 U26.6 | length 796.7
  Top Layer w5.3: v1(1091.37,1290) U26.6@1136.73,1290
  SIG 1 w4.75: v1(451.14,1429.87) 591.01,1290 v1(1091.37,1290)
  Bottom Layer w5.3: v1(451.14,1429.87) 464.4,1443.13 U24.37@464.4,1477.52
AM263_TEMPCAL: U1.U1
AM263_TMS: R325.1 U1.D5 | length 3055.2
  Top Layer w5.3: v1(1481.5,1402.4) R325.1@1481.5,1434.92
  Top Layer w10: v1(3507.37,1154.06) U1.D5@3523.12,1138.31
  SIG 1 w4.75: v1(1481.5,1402.4) 1569.17,1490.07 1724.63,1490.07 1786.81,1552.26 2185,1552.26 2305.1,1432.16 2305.1,1310.49 2332.32,1283.27 2606.46,1283.27 2671.64,1348.45 2909.96,1348.45 3169.02,1607.5 3169.02,1667.65 3185.01,1683.64 3344.8,1683.64 3367.29,1661.16 3487.53,1661.16 3519.19,1629.5 3519.19,1570.89 3490.32,1542.02 3490.32,1343.54 3491.47,1342.39 3491.47,1264.29 3491.47,1169.96 v1(3507.37,1154.06)
AM263_TMS_R: R325.2 U25.6 | length 109.2
  Top Layer w5.3: U25.6@1352.36,1473.86 1414.43,1473.86 1434.25,1454.05 R325.2@1434.25,1434.92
